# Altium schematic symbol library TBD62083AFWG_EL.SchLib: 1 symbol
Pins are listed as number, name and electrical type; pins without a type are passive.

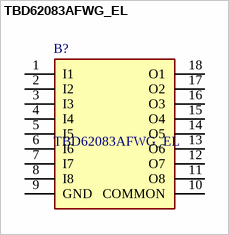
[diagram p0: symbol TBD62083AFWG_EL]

## TBD62083AFWG_EL
designator B?
Gate Drivers DMOS Transistor Array 8-CH, 50V/0.5A; Manufacturer_Name: Toshiba; Manufacturer_Part_Number: TBD62083AFWG,EL; Geometry.Height: 2.85mm
footprint SOIC127P1032X285-18N
pins: 1 I1, 2 I2, 3 I3, 4 I4, 5 I5, 6 I6, 7 I7, 8 I8, 9 GND, 10 COMMON, 11 O8, 12 O7, 13 O6, 14 O5, 15 O4, 16 O3, 17 O2, 18 O1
